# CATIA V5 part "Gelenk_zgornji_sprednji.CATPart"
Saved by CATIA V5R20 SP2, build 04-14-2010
Part number: Gelenk_zgornji_sprednji
Bounding box of the stored display mesh (mm): x -4.8 to 4.8, y 0 to 25, z -29.795 to 29.795
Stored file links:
  C:\Documents and Settings\Administrator\My Documents\Hobi_dokumenti\CAD_CNC\Clap_CATIA\Gelenk_zgornji_sprednji.CATPart
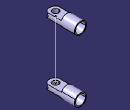
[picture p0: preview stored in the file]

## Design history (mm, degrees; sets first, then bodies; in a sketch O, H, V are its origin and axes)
Set1
  Point1: type Center, Curve edge [face of Pocket1 from Sketch2.L5 | face of Pocket2 from Sketch3.A1]
  Point2: type Center, Curve edge [face of Mirror1 | face of Mirror1]
  Line1: type PtPt, FirstPoint Point2, SecondPoint Point1
Body1 (main body)
  Sketch1 on xy-plane, origin (0, 0, 0), H (1, 0, 0), V (0, 1, 0)
    line L1 (0, 0) -> (-4.8, 0)
    line L2 (-4.8, 0) -> (-4.8, 25)
    line L3 (-4.8, 25) -> (0, 25)
    line L4 (0, 25) -> (0, 0)
    point P1 (-4.8, 0)
    point P3 (0, 25)
    distance O P1 = 4.8
    distance P3 O = 25
    horizontal: L1 H, L3 H
    vertical: L2 V, L4 V
    perpendicularity: L1 L2
  Shaft1: profile Sketch1, axis Sketch1.L4, angle 360
  Translate1: Direction xy-plane, Length 25, ToTransfor Shaft1
  Sketch2 on yz-plane, origin (0, 0, 0), H (0, 1, 0), V (0, 0, 1)
    line L1 (-3.9957, 30.9) -> (14, 30.9)
    line L2 (14, 30.9) -> (14, 26.9)
    line L3 (14, 26.9) -> (-3.9957, 26.9)
    line L4 (-3.9957, 26.9) -> (-3.9957, 30.9)
    point P5 (-3.9957, 23.1)
    line L5 (-3.9957, 23.1) -> (14, 23.1)
    line L6 (14, 23.1) -> (14, 19.1)
    line L7 (14, 19.1) -> (-3.9957, 19.1)
    line L8 (-3.9957, 19.1) -> (-3.9957, 23.1)
    point P7 (14, 19.1)
    reference projected line E1 through (0, 25) direction (1, 0) from axis of face of Shaft1 from Sketch1.L2
    reference projected line E2 through (0, 25) direction (1, 0) from axis of face of Shaft1 from Sketch1.L2
    reference projected line E3 (0, 29.8) -> (0, 20.2) from edge [face of Shaft1 from Sketch1.L1 | face of Shaft1 from Sketch1.L2]
    distance E1 L5 = 1.9
    distance E2 L3 = 1.9
    distance E3 L2 = 14
    length L8 = 4
    length L4 = 4
    horizontal: L1 H, L3 H, L5 H, L7 H
    vertical: L2 V, L4 V, L6 V, L8 V
    coincidence: P5 L4, P7 L2
  Pocket1: profile Sketch2, direction (1, 0, 0), length 20, mirrored extent
  Sketch3 on xy-plane, origin (0, 0, 0), H (1, 0, 0), V (0, 1, 0)
    circle A1 centre (0, 4.9462) radius 2.5
    point P1 (0, 4.9462)
    arc A2 centre (0, 4.9462) radius 5 from (-5, 4.9462) to (5, 4.9462) ccw
    line L1 (8.2326, 4.9462) -> (5, 4.9462)
    line L2 (-8.288, 4.9462) -> (-8.288, -1.7558)
    line L3 (-8.288, -1.7558) -> (8.2326, -1.7558)
    line L4 (8.2326, -1.7558) -> (8.2326, 4.9462)
    point P6 (-5, 4.9462)
    line L5 (-5, 4.9462) -> (-8.288, 4.9462)
    radius A1 = 2.5
    radius A2 = 5
    coincidence: P1 V, L1 P6
    horizontal: L1 H, L3 H, L5 H
    vertical: L2 V, L4 V
  Pocket2: profile Sketch3, direction (0, 0, 1), through (limit type 6)
  Mirror1: of the body so far, about xy-plane
  Sketch4 on face of Mirror1, origin (0, 25, 0), H (-1, 0, 0), V (0, 0, 1)
    circle A1 centre (0, 25) radius 4
    point P1 (0, 25)
    circle A2 centre (0, -25) radius 4
    point P2 (0, -25)
    reference intersected line E1 through (0, 0) direction (-1, 0) from xy-plane
    reference intersected line E2 through (0, 0) direction (0, -1) from yz-plane
    radius A1 = 4
    radius A2 = 4
    distance P2 H = 25
    distance P1 H = 25
    coincidence: P1 V, P2 V, E2 P1
    vertical: E2 V
    horizontal: E1 H
  Pocket3: profile Sketch4, direction (0, -1, 0), length 10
